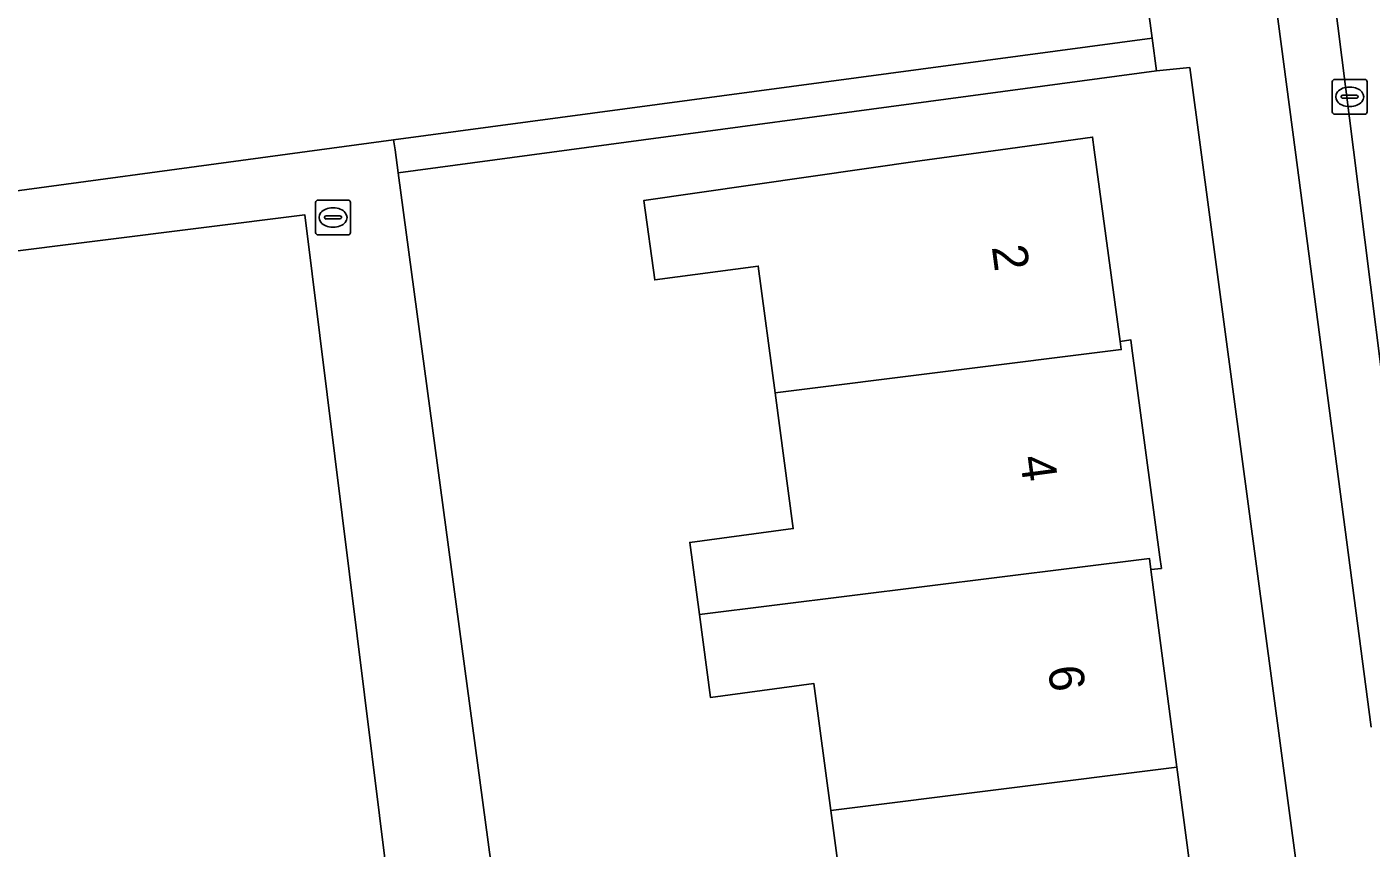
# Model space of a CAD drawing. Extents: x 163426 to 164192, y 380329 to 381641.
# Drawn here: x 163502.62 to 163541.16, y 381479.99 to 381503.52 of the extents above; entities that cross this region are included whole.
import ezdxf

# ---------------------------------------------------------------- set-up
doc = ezdxf.new("R2010")
doc.units = 0
for name, color, linetype in [('IMGEO_Erf', 7, 'Continuous'), ('IMGEO_Kolk', 7, 'Continuous'), ('IMGEO_Pand', 7, 'Continuous'), ('IMGEO_Pand_nummerreeks', 7, 'Continuous'), ('IMGEO_Parkeervlak_open', 7, 'Continuous'), ('IMGEO_Rijbaan_lokaal_open', 7, 'Continuous'), ('IMGEO_Voetpad_open', 7, 'Continuous')]:
    doc.layers.add(name, color=color, linetype=linetype)

msp = doc.modelspace()

# ---------------------------------------------------------------- linework, layer by layer
at = {"layer": 'IMGEO_Erf'}
for points in [[(163532.089, 381524.073), (163500.343, 381519.8), (163500.304, 381520.404), (163500, 381520.363), (163472.627, 381516.638), (163466.066, 381515.775), (163468.184, 381499.951), (163468.966, 381494.225), (163500, 381498.51), (163511.008, 381500), (163513.136, 381500.288), (163534.881, 381503.195)], [(163539.823, 381462.212), (163541.312, 381462.422), (163536.277, 381500), (163535.961, 381502.355), (163535.005, 381502.264), (163513.264, 381499.338), (163523.981, 381419.703), (163545.149, 381422.545)]]:
    msp.add_lwpolyline(points, close=True, dxfattribs=at)
msp.add_lwpolyline([(163526.179, 381477.268), (163525.673, 381481.067), (163525.188, 381484.701), (163522.219, 381484.305), (163521.901, 381486.681), (163521.625, 381488.748), (163524.595, 381489.143), (163524.076, 381493.035), (163523.592, 381496.664), (163520.623, 381496.269), (163520.311, 381498.548), (163528.223, 381499.681), (163530.539, 381500), (163533.175, 381500.363), (163533.224, 381500), (163533.968, 381494.509), (163534.274, 381494.551), (163534.306, 381494.31), (163535.105, 381488.326), (163535.148, 381488.003), (163534.846, 381487.974), (163535.597, 381482.304), (163536.39, 381476.319)], dxfattribs=at)
at = {"layer": 'IMGEO_Kolk'}
for p, q in [((163540.048, 381501.09), (163540.048, 381501.942)), ((163540.123, 381502.016), (163540.975, 381502.016)), ((163540.536, 381501.796), (163540.561, 381501.796)), ((163541.049, 381501.942), (163541.049, 381501.09)), ((163540.307, 381501.51), (163540.307, 381501.522)), ((163540.745, 381501.473), (163540.347, 381501.473)), ((163540.35, 381501.559), (163540.748, 381501.559)), ((163540.791, 381501.522), (163540.791, 381501.51)), ((163540.975, 381501.016), (163540.123, 381501.016)), ((163540.559, 381501.236), (163540.534, 381501.236)), ((163510.973, 381498.558), (163511.825, 381498.558)), ((163510.898, 381497.632), (163510.898, 381498.484)), ((163511.386, 381498.338), (163511.411, 381498.338)), ((163511.899, 381498.484), (163511.899, 381497.632)), ((163511.157, 381498.052), (163511.157, 381498.064)), ((163511.595, 381498.015), (163511.197, 381498.015)), ((163511.2, 381498.101), (163511.598, 381498.101)), ((163511.641, 381498.064), (163511.641, 381498.052)), ((163511.825, 381497.558), (163510.973, 381497.558)), ((163511.409, 381497.778), (163511.384, 381497.778))]:
    msp.add_line(p, q, dxfattribs=at)
for points in [[(163540.048, 381501.09), (163540.048, 381501.942)], [(163540.123, 381502.016), (163540.975, 381502.016)], [(163541.049, 381501.942), (163541.049, 381501.09)], [(163540.975, 381501.016), (163540.123, 381501.016)], [(163510.973, 381498.558), (163511.825, 381498.558)], [(163510.898, 381497.632), (163510.898, 381498.484)], [(163511.899, 381498.484), (163511.899, 381497.632)], [(163511.825, 381497.558), (163510.973, 381497.558)]]:
    msp.add_lwpolyline(points, dxfattribs=at)
for centre, radius, start, end in [((163540.125, 381501.94), 0.0765, 91.552, 178.448), ((163540.125, 381501.94), 0.0765, 91.552, 178.448), ((163540.973, 381501.94), 0.0765, 1.552, 88.448), ((163540.973, 381501.94), 0.0765, 1.552, 88.448), ((163540.347, 381501.519), 0.0403, 85.8775, 175.7526), ((163540.344, 381501.509), 0.0366, 178.938, 274.7102), ((163540.748, 381501.516), 0.043, 264.8664, 352.4533), ((163540.752, 381501.521), 0.0386, 1.7309, 96.639), ((163540.125, 381501.092), 0.0765, 181.552, 268.448), ((163540.125, 381501.092), 0.0765, 181.552, 268.448), ((163540.973, 381501.092), 0.0765, 271.552, 358.448), ((163540.973, 381501.092), 0.0765, 271.552, 358.448), ((163510.975, 381498.482), 0.0765, 91.552, 178.448), ((163510.975, 381498.482), 0.0765, 91.552, 178.448), ((163511.823, 381498.482), 0.0765, 1.552, 88.448), ((163511.823, 381498.482), 0.0765, 1.552, 88.448), ((163511.197, 381498.061), 0.0403, 85.8775, 175.7526), ((163511.194, 381498.051), 0.0366, 178.938, 274.7102), ((163511.598, 381498.058), 0.043, 264.8664, 352.4533), ((163511.602, 381498.063), 0.0386, 1.7309, 96.639), ((163510.975, 381497.634), 0.0765, 181.552, 268.448), ((163510.975, 381497.634), 0.0765, 181.552, 268.448), ((163511.823, 381497.634), 0.0765, 271.552, 358.448), ((163511.823, 381497.634), 0.0765, 271.552, 358.448)]:
    msp.add_arc(centre, radius, start, end, dxfattribs=at)
for centre, major_axis, ratio, start_param, end_param in [((163540.535, 381501.516), (-0.387, 0.002), 0.722429, 4.712389, 7.853982), ((163540.56, 381501.516), (-0.39, 0.002), 0.717154, 1.570796, 4.712389), ((163511.385, 381498.058), (-0.387, 0.002), 0.722429, 4.712389, 7.853982), ((163511.41, 381498.058), (-0.39, 0.002), 0.717154, 1.570796, 4.712389)]:
    msp.add_ellipse(centre, major_axis=major_axis, ratio=ratio, start_param=start_param, end_param=end_param, dxfattribs=at)
at = {"layer": 'IMGEO_Pand'}
for points in [[(163533.224, 381500), (163533.175, 381500.363), (163530.539, 381500), (163528.223, 381499.681), (163520.311, 381498.548), (163520.623, 381496.269), (163523.592, 381496.664), (163524.076, 381493.035), (163534, 381494.272), (163533.968, 381494.509)], [(163534.306, 381494.31), (163534.274, 381494.551), (163533.968, 381494.509), (163534, 381494.272), (163524.076, 381493.035), (163524.595, 381489.143), (163521.625, 381488.748), (163521.901, 381486.681), (163534.804, 381488.288), (163534.846, 381487.974), (163535.148, 381488.003), (163535.105, 381488.326)], [(163534.846, 381487.974), (163534.804, 381488.288), (163521.901, 381486.681), (163522.219, 381484.305), (163525.188, 381484.701), (163525.673, 381481.067), (163535.597, 381482.304)], [(163535.597, 381482.304), (163525.673, 381481.067), (163526.179, 381477.268), (163523.209, 381476.873), (163523.497, 381474.713), (163536.39, 381476.319)]]:
    msp.add_lwpolyline(points, close=True, dxfattribs=at)
at = {"layer": 'IMGEO_Parkeervlak_open'}
for points in [[(163540.658, 381500), (163538.748, 381515.131)], [(163537.364, 381512.278), (163538.982, 381500), (163541.163, 381483.452)], [(163543.08, 381480.808), (163540.658, 381500)]]:
    msp.add_lwpolyline(points, dxfattribs=at)
at = {"layer": 'IMGEO_Rijbaan_lokaal_open'}
for points in [[(163547.714, 381448.459), (163552.773, 381449.148), (163551.848, 381456.16), (163547.979, 381484.273), (163547.83, 381485.368), (163545.852, 381500), (163542.971, 381521.306), (163542.879, 381522.123), (163542.729, 381523.405), (163542.764, 381523.704), (163537.726, 381523.034), (163537.691, 381522.857), (163537.994, 381521.009), (163538.748, 381515.131), (163540.658, 381500), (163543.08, 381480.808), (163547.416, 381450.538)], [(163531.559, 381329.55), (163531.559, 381329.55), (163536.034, 381330.138), (163524.164, 381418.345), (163523.981, 381419.703), (163513.264, 381499.338), (163513.175, 381500), (163513.136, 381500.288), (163511.008, 381500), (163500, 381498.51), (163468.966, 381494.225), (163468.645, 381494.168), (163468.815, 381492.913), (163468.816, 381492.902), (163510.586, 381498.135)]]:
    msp.add_lwpolyline(points, close=True, dxfattribs=at)
at = {"layer": 'IMGEO_Voetpad_open'}
for points in [[(163538.748, 381515.131), (163537.994, 381521.009), (163537.691, 381522.857), (163537.726, 381523.034), (163537.586, 381523.962), (163537.28, 381526.001), (163532.089, 381524.073), (163534.881, 381503.195), (163535.005, 381502.264), (163535.961, 381502.355), (163536.277, 381500), (163541.312, 381462.422), (163539.823, 381462.212), (163545.149, 381422.545), (163545.331, 381421.187), (163551.459, 381375.552), (163552.956, 381375.749), (163557.372, 381342.692), (163557.774, 381339.564)], [(163541.163, 381483.452), (163538.982, 381500), (163537.364, 381512.278)]]:
    msp.add_lwpolyline(points, dxfattribs=at)
msp.add_lwpolyline([(163535.005, 381502.264), (163534.881, 381503.195), (163513.136, 381500.288), (163513.175, 381500), (163513.264, 381499.338)], close=True, dxfattribs=at)

# ---------------------------------------------------------------- texts
at = {"layer": 'IMGEO_Pand_nummerreeks'}
for s, p in [('2', (163530.285, 381497.217)), ('4', (163531.089, 381491.188)), ('6', (163531.892, 381485.162))]:
    msp.add_text(s, height=1, rotation=277.5915, dxfattribs=at).set_placement(p)

doc.saveas('drawing.dxf')
